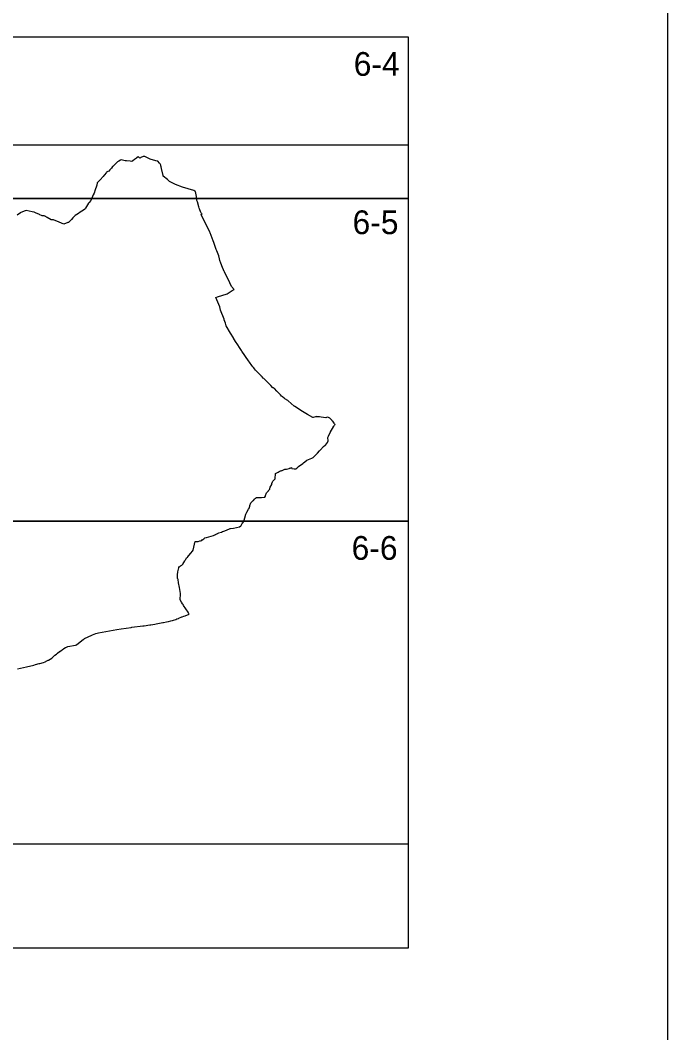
# Model space of a CAD drawing. Extents: x -447352 to -425530, y -1135906 to -1125104.
# Drawn here: x -441555.1 to -441304.5, y -1126663.9 to -1126271.9 of the extents above; entities that cross this region are included whole.
import ezdxf

# ---------------------------------------------------------------- set-up
doc = ezdxf.new("R2010")
doc.units = 0
for name, color, linetype in [('Vrstva 1', 7, 'Continuous'), ('Vrstva 10', 7, 'Continuous'), ('Vrstva 4', 7, 'Continuous')]:
    doc.layers.add(name, color=color, linetype=linetype)

msp = doc.modelspace()

# ---------------------------------------------------------------- linework, layer by layer
at = {"layer": 'Vrstva 1'}
msp.add_lwpolyline([(-442789.49, -1126016.81), (-442789.49, -1127066.81), (-441304.49, -1127066.81), (-441304.49, -1126016.81)], close=True, dxfattribs=at)
msp.add_lwpolyline([(-441556.2, -1126523.09), (-441552.66, -1126522.22), (-441549.89, -1126521.55), (-441549.22, -1126521.34), (-441547.73, -1126520.98), (-441547.52, -1126520.92), (-441546.09, -1126520.53), (-441545.49, -1126520.27), (-441545.27, -1126520.17), (-441545.11, -1126520.11), (-441544.29, -1126519.66), (-441544.23, -1126519.62), (-441542.92, -1126518.84), (-441541.77, -1126517.79), (-441541.12, -1126517.29), (-441540.99, -1126517.18), (-441540.97, -1126517.17), (-441540.81, -1126517.04), (-441540.66, -1126516.94), (-441539.86, -1126516.38), (-441539.8, -1126516.34), (-441539.73, -1126516.29), (-441539.22, -1126515.94), (-441538.85, -1126515.68), (-441538.19, -1126515.22), (-441537.6, -1126514.81), (-441537.44, -1126514.84), (-441537.43, -1126514.84), (-441537.41, -1126514.82), (-441536.68, -1126514.43), (-441533.72, -1126513.85), (-441533.3, -1126513.7), (-441531.27, -1126512.07), (-441530.8, -1126511.73), (-441530.77, -1126511.71), (-441530.41, -1126511.45), (-441530.23, -1126511.33), (-441528.84, -1126510.63), (-441527.43, -1126509.99), (-441527.13, -1126509.84), (-441525.87, -1126509.38), (-441524.87, -1126509.13), (-441519.16, -1126508.07), (-441517.74, -1126507.81), (-441516.03, -1126507.56), (-441512.16, -1126506.99), (-441511.92, -1126506.96), (-441507.62, -1126506.44), (-441507.09, -1126506.38), (-441504.94, -1126506.02), (-441504.62, -1126505.97), (-441502.96, -1126505.7), (-441502.56, -1126505.63), (-441501.15, -1126505.34), (-441499.86, -1126505.07), (-441499.65, -1126505.03), (-441498.48, -1126504.8), (-441497.81, -1126504.67), (-441497.79, -1126504.67), (-441496.88, -1126504.46), (-441496.81, -1126504.44), (-441496.16, -1126504.28), (-441495.81, -1126504.17), (-441494.92, -1126503.88), (-441494.48, -1126503.73), (-441493.83, -1126503.49), (-441493.71, -1126503.45), (-441492.62, -1126502.96), (-441492.62, -1126502.96), (-441492.5, -1126502.92), (-441491.85, -1126502.69), (-441491.76, -1126502.66), (-441491.33, -1126502.5), (-441489.67, -1126501.92), (-441489.69, -1126501.87), (-441489.8, -1126501.7), (-441489.96, -1126501.47), (-441490.18, -1126501.15), (-441491.88, -1126498.51), (-441492.09, -1126498.16), (-441492.26, -1126497.89), (-441492.7, -1126497.18), (-441493.23, -1126496.33), (-441493.07, -1126493.97), (-441493.06, -1126493.88), (-441493.45, -1126491.58), (-441493.45, -1126491.56), (-441493.46, -1126491.54), (-441493.46, -1126491.54), (-441493.46, -1126491.51), (-441493.87, -1126489.68), (-441493.88, -1126489.49), (-441493.94, -1126488.69), (-441494.04, -1126488.41), (-441494.05, -1126488.39), (-441494.16, -1126488.17), (-441494.2, -1126488.09), (-441494.21, -1126487.71), (-441494.24, -1126487.01), (-441494.19, -1126486.52), (-441494.19, -1126486.5), (-441494.1, -1126485.64), (-441494.08, -1126485.53), (-441493.79, -1126483.89), (-441493.71, -1126483.81), (-441493.41, -1126483.47), (-441493.35, -1126483.4), (-441493.09, -1126483.28), (-441493.03, -1126483.22), (-441492.77, -1126483.02), (-441492.54, -1126482.84), (-441492.33, -1126482.68), (-441492.27, -1126482.64), (-441492.19, -1126482.51), (-441492.11, -1126482.39), (-441492, -1126482.22), (-441491.78, -1126481.89), (-441491.36, -1126481.24), (-441491.23, -1126480.99), (-441491.22, -1126480.98), (-441491.08, -1126480.69), (-441491.03, -1126480.6), (-441490.85, -1126480.27), (-441490.71, -1126480.12), (-441490.41, -1126479.81), (-441490.24, -1126479.63), (-441489.96, -1126479.28), (-441489.83, -1126479.11), (-441489.14, -1126478.26), (-441488.48, -1126477.45), (-441488.19, -1126477.09), (-441487.95, -1126475.92), (-441487.89, -1126475.69), (-441487.82, -1126475.41), (-441487.5, -1126474.1), (-441487.42, -1126473.82), (-441487.42, -1126473.79), (-441487.4, -1126473.74), (-441487.24, -1126473.73), (-441487.22, -1126473.73), (-441486.98, -1126473.73), (-441486.29, -1126473.71), (-441486.28, -1126473.71), (-441486.25, -1126473.71), (-441485.57, -1126473.53), (-441485.37, -1126473.47), (-441484.95, -1126473.36), (-441484.93, -1126473.35), (-441484.87, -1126473.29), (-441484.57, -1126473.01), (-441484.45, -1126472.93), (-441484.11, -1126472.67), (-441483.69, -1126472.35), (-441483.62, -1126472.33), (-441483.06, -1126472.17), (-441480.36, -1126471.41), (-441479.77, -1126471.14), (-441479.44, -1126470.98), (-441479.39, -1126470.96), (-441479.29, -1126470.91), (-441478.93, -1126470.73), (-441478.88, -1126470.71), (-441478.85, -1126470.69), (-441478.84, -1126470.69), (-441478.81, -1126470.67), (-441478.5, -1126470.52), (-441478.44, -1126470.48), (-441478.33, -1126470.43), (-441477.25, -1126470.1), (-441476.82, -1126469.92), (-441476.3, -1126469.7), (-441475.29, -1126469.29), (-441473.87, -1126468.66), (-441473.73, -1126468.65), (-441472.6, -1126468.6), (-441470.2, -1126468.04), (-441469.67, -1126467.64), (-441469.6, -1126467.52), (-441469.51, -1126467.34), (-441469.25, -1126466.83), (-441468.9, -1126466.4), (-441468.88, -1126466.37), (-441468.67, -1126466.08), (-441468.56, -1126465.92), (-441468.55, -1126465.91), (-441468.01, -1126464.13), (-441468, -1126464.1), (-441467.8, -1126463.15), (-441467.54, -1126462.69), (-441467.35, -1126462.36), (-441466.8, -1126461.24), (-441466.42, -1126460.73), (-441466.39, -1126460.6), (-441466.32, -1126460.3), (-441466.29, -1126460.16), (-441466.23, -1126459.91), (-441466.21, -1126459.81), (-441465.89, -1126458.8), (-441465.88, -1126458.79), (-441465.59, -1126458.51), (-441464.93, -1126457.88), (-441464.88, -1126457.83), (-441464.41, -1126457.35), (-441464.15, -1126457.09), (-441464.05, -1126456.98), (-441463.68, -1126456.66), (-441463.64, -1126456.66), (-441463.63, -1126456.66), (-441463.22, -1126456.65), (-441463.05, -1126456.66), (-441462.42, -1126456.68), (-441461.71, -1126456.68), (-441460.74, -1126456.59), (-441460.71, -1126456.59), (-441460.46, -1126456.56), (-441460.24, -1126456.2), (-441460.19, -1126456.07), (-441460.17, -1126456.02), (-441460.15, -1126455.96), (-441459.79, -1126454.94), (-441459.65, -1126454.77), (-441459.55, -1126454.66), (-441459.51, -1126454.62), (-441459.45, -1126454.54), (-441459.33, -1126454.41), (-441459.06, -1126454.09), (-441458.97, -1126453.99), (-441458.87, -1126453.87), (-441458.53, -1126453.48), (-441458.46, -1126453.09), (-441458.4, -1126452.78), (-441458.33, -1126452.65), (-441457.78, -1126451.73), (-441457.67, -1126451.34), (-441457.48, -1126450.64), (-441457.36, -1126450.35), (-441457.07, -1126450.08), (-441456.52, -1126449.57), (-441456.45, -1126449.51), (-441456.35, -1126447.4), (-441455.33, -1126446.91), (-441454.93, -1126446.7), (-441454.68, -1126446.57), (-441454.39, -1126446.41), (-441454.17, -1126446.33), (-441453.83, -1126446.2), (-441453.78, -1126446.19), (-441452.69, -1126445.78), (-441452.68, -1126445.78), (-441452.19, -1126445.72), (-441452.11, -1126445.7), (-441451.08, -1126445.44), (-441450.93, -1126445.4), (-441450.84, -1126445.37), (-441450.67, -1126445.32), (-441450.14, -1126445.15), (-441450.14, -1126445.15), (-441450.13, -1126445.16), (-441450.13, -1126445.16), (-441450.1, -1126445.22), (-441449.97, -1126445.44), (-441449.09, -1126445.54), (-441448.89, -1126445.56), (-441448.53, -1126445.6), (-441448.44, -1126445.56), (-441448.01, -1126445.38), (-441447.36, -1126444.67), (-441445.72, -1126443.51), (-441445.63, -1126443.44), (-441445.46, -1126443.33), (-441444.95, -1126442.91), (-441444.2, -1126442.31), (-441442.93, -1126441.74), (-441442.31, -1126441.47), (-441441.77, -1126441.23), (-441441.71, -1126441.2), (-441440.06, -1126439.53), (-441439.22, -1126438.64), (-441438.86, -1126438.26), (-441437.67, -1126436.9), (-441437.07, -1126436.44), (-441437.02, -1126436.4), (-441436.18, -1126435.39), (-441435.98, -1126434.82), (-441436.07, -1126433.49), (-441435.85, -1126433), (-441435.21, -1126431.55), (-441433.75, -1126429.07), (-441433.72, -1126429.02), (-441433.72, -1126429.02), (-441433.7, -1126428.99), (-441433.67, -1126428.95), (-441433.52, -1126428.76), (-441433.26, -1126428.42), (-441433.52, -1126428.12), (-441433.66, -1126427.9), (-441434.13, -1126427.16), (-441434.33, -1126426.97), (-441434.48, -1126426.81), (-441434.67, -1126426.61), (-441435.25, -1126426.04), (-441436.1, -1126425.57), (-441436.55, -1126425.75), (-441436.88, -1126425.87), (-441438.63, -1126425.6), (-441439.24, -1126425.51), (-441439.38, -1126425.5), (-441439.97, -1126425.48), (-441440.35, -1126425.43), (-441440.51, -1126425.4), (-441440.55, -1126425.4), (-441440.58, -1126425.39), (-441440.58, -1126425.39), (-441440.61, -1126425.4), (-441440.71, -1126425.43), (-441440.84, -1126425.46), (-441441.74, -1126425.7), (-441441.81, -1126425.67), (-441443.88, -1126424.63), (-441445.9, -1126423.35), (-441448.81, -1126421.53), (-441448.97, -1126421.39), (-441449.01, -1126421.36), (-441449.1, -1126421.28), (-441450.24, -1126420.35), (-441451.39, -1126419.3), (-441451.5, -1126419.2), (-441452.71, -1126418.44), (-441452.99, -1126418.21), (-441453.62, -1126417.71), (-441453.93, -1126417.47), (-441454.43, -1126416.94), (-441455.15, -1126416.18), (-441455.3, -1126416.02), (-441455.76, -1126415.53), (-441456.73, -1126414.5), (-441456.93, -1126414.39), (-441456.93, -1126414.39), (-441457.11, -1126414.3), (-441457.31, -1126414.2), (-441458.14, -1126413.37), (-441458.77, -1126412.74), (-441459.95, -1126411.57), (-441460.88, -1126410.63), (-441461.04, -1126410.48), (-441461.48, -1126410.03), (-441461.72, -1126409.79), (-441461.81, -1126409.7), (-441461.85, -1126409.66), (-441462.37, -1126409.14), (-441463.01, -1126408.49), (-441463.09, -1126408.41), (-441463.11, -1126408.39), (-441463.26, -1126408.24), (-441464.09, -1126407.4), (-441464.47, -1126406.9), (-441464.75, -1126406.53), (-441465.07, -1126406.1), (-441465.43, -1126405.62), (-441466.38, -1126404.36), (-441466.75, -1126403.82), (-441469.29, -1126400.08), (-441469.46, -1126399.82), (-441470.23, -1126398.63), (-441470.9, -1126397.62), (-441471.74, -1126396.29), (-441472.54, -1126395.02), (-441472.62, -1126394.89), (-441473.71, -1126393.04), (-441475.39, -1126390.19), (-441475.39, -1126390.18), (-441475.39, -1126390.18), (-441475.4, -1126390.18), (-441475.73, -1126389.2), (-441476.18, -1126387.9), (-441476.24, -1126387.7), (-441477.62, -1126384.19), (-441477.91, -1126382.94), (-441479.39, -1126379.26), (-441478.76, -1126379.06), (-441475.04, -1126377.82), (-441473.07, -1126376.6), (-441472.89, -1126376.49), (-441472.83, -1126376.45), (-441472.63, -1126376.33), (-441472.36, -1126376.16), (-441473.28, -1126374.97), (-441474.69, -1126372.19), (-441475.44, -1126370.72), (-441475.97, -1126369.56), (-441475.99, -1126369.52), (-441476.05, -1126369.39), (-441476.06, -1126369.36), (-441476.08, -1126369.33), (-441476.12, -1126369.24), (-441476.45, -1126368.51), (-441476.77, -1126367.72), (-441477.48, -1126365.95), (-441477.89, -1126364.91), (-441478.04, -1126364.28), (-441478.3, -1126363.15), (-441479.04, -1126361.26), (-441479.24, -1126360.66), (-441480.18, -1126358.03), (-441480.45, -1126357.31), (-441481.64, -1126354.22), (-441481.71, -1126354.04), (-441481.74, -1126353.96), (-441485.09, -1126347.15), (-441484.78, -1126347.01), (-441484.76, -1126347), (-441484.86, -1126346.83), (-441484.94, -1126346.73), (-441485.11, -1126346.5), (-441485.17, -1126346.42), (-441485.78, -1126344.94), (-441485.83, -1126344.65), (-441485.93, -1126344.19), (-441485.94, -1126344.13), (-441486.45, -1126342.29), (-441486.75, -1126341.66), (-441486.76, -1126341.58), (-441486.8, -1126341.22), (-441486.94, -1126340.13), (-441487.22, -1126338.29), (-441487.28, -1126338.27), (-441487.58, -1126338.17), (-441487.96, -1126337.91), (-441487.97, -1126337.91), (-441492.27, -1126336.5), (-441495.06, -1126335.52), (-441496.37, -1126334.9), (-441497.34, -1126334.34), (-441498.06, -1126333.56), (-441499.74, -1126332.29), (-441499.8, -1126331.99), (-441500.38, -1126329.29), (-441500.53, -1126328.75), (-441500.71, -1126328.24), (-441500.76, -1126328.08), (-441501.01, -1126327.56), (-441501.26, -1126327.25), (-441501.84, -1126326.56), (-441502.59, -1126326.35), (-441504.77, -1126325.69), (-441506.86, -1126324.73), (-441507.48, -1126324.73), (-441508.43, -1126325.1), (-441508.56, -1126325.19), (-441508.63, -1126325.24), (-441508.77, -1126325.34), (-441508.81, -1126325.37), (-441508.83, -1126325.35), (-441509.04, -1126325.1), (-441509.29, -1126324.82), (-441509.37, -1126324.72), (-441509.46, -1126324.76), (-441509.97, -1126325.15), (-441510.16, -1126325.3), (-441510.83, -1126325.82), (-441511.58, -1126326.38), (-441511.92, -1126326.6), (-441512.51, -1126326.56), (-441513.99, -1126326.41), (-441514.45, -1126326.32), (-441516.04, -1126326), (-441516.34, -1126326.11), (-441516.9, -1126326.46), (-441517.45, -1126326.78), (-441517.94, -1126327.24), (-441518.47, -1126327.73), (-441518.87, -1126328.12), (-441518.88, -1126328.13), (-441519.21, -1126328.47), (-441519.34, -1126328.61), (-441519.85, -1126329.16), (-441520.3, -1126329.71), (-441520.46, -1126329.9), (-441520.82, -1126330.33), (-441521.56, -1126330.66), (-441521.58, -1126330.66), (-441521.78, -1126330.91), (-441522.64, -1126331.93), (-441523.02, -1126332.38), (-441524.15, -1126333.74), (-441524.16, -1126333.75), (-441525.4, -1126334.92), (-441525.52, -1126335.76), (-441525.57, -1126336.13), (-441525.61, -1126336.23), (-441526.09, -1126337.58), (-441526.53, -1126338.82), (-441526.56, -1126338.9), (-441526.86, -1126339.59), (-441527.79, -1126341.77), (-441527.81, -1126341.78), (-441528.38, -1126342.46), (-441528.68, -1126342.81), (-441528.68, -1126342.82), (-441529.02, -1126343.36), (-441529.89, -1126344.75), (-441529.98, -1126344.89), (-441530.15, -1126345.02), (-441530.68, -1126345.41), (-441531.29, -1126345.86), (-441531.29, -1126345.86), (-441532.26, -1126346.49), (-441532.39, -1126346.58), (-441532.57, -1126346.7), (-441533.87, -1126347.56), (-441533.88, -1126347.57), (-441534.14, -1126347.83), (-441534.26, -1126347.95), (-441534.48, -1126348.18), (-441534.76, -1126348.46), (-441535.33, -1126349.03), (-441536.49, -1126350.19), (-441536.69, -1126350.27), (-441538.19, -1126350.84), (-441541, -1126349.72), (-441541, -1126349.73), (-441541.01, -1126349.75), (-441541.92, -1126349.37), (-441542.23, -1126349.24), (-441542.25, -1126349.24), (-441542.64, -1126349.24), (-441543.12, -1126349.24), (-441544.68, -1126348.25), (-441544.94, -1126348.12), (-441545.23, -1126347.96), (-441545.29, -1126347.93), (-441545.33, -1126347.91), (-441545.87, -1126347.68), (-441545.92, -1126347.68), (-441545.93, -1126347.68), (-441546.08, -1126347.67), (-441546.2, -1126347.66), (-441546.51, -1126347.64), (-441546.53, -1126347.64), (-441546.53, -1126347.64), (-441546.64, -1126347.6), (-441546.88, -1126347.5), (-441547.48, -1126347.25), (-441547.64, -1126347.18), (-441549.16, -1126346.45), (-441549.78, -1126346.27), (-441550.45, -1126346.07), (-441552.77, -1126345.64), (-441552.78, -1126345.64), (-441553.18, -1126345.75), (-441554.92, -1126346.33), (-441555.05, -1126346.44), (-441556.26, -1126347.4)], dxfattribs=at)
at = {"layer": 'Vrstva 10'}
msp.add_lwpolyline([(-441404.9, -1126320.23), (-441404.9, -1126631.21), (-441737.77, -1126631.21), (-441737.77, -1126465.91), (-441717.4, -1126465.91), (-441717.4, -1126340.91), (-441717.4, -1126320.23), (-441404.9, -1126320.23)], dxfattribs=at)
at = {"layer": 'Vrstva 4'}
msp.add_line((-441717.4, -1126278.41), (-441404.9, -1126278.41), dxfattribs=at)
msp.add_lwpolyline([(-441404.9, -1126278.41), (-441404.9, -1126340.91), (-441561.15, -1126340.91), (-441561.15, -1126278.41)], dxfattribs=at)
for points in [[(-441404.9, -1126340.91), (-441404.9, -1126465.91), (-441561.15, -1126465.91), (-441561.15, -1126340.91)], [(-441404.9, -1126465.91), (-441404.9, -1126590.91), (-441561.15, -1126590.91), (-441561.15, -1126465.91)]]:
    msp.add_lwpolyline(points, close=True, dxfattribs=at)

# ---------------------------------------------------------------- texts
at = {"layer": 'Vrstva 1'}
for s, p in [('6-4', (-441426.03, -1126293.46)), ('6-5', (-441426.48, -1126354.75)), ('6-6', (-441426.85, -1126480.82))]:
    msp.add_text(s, height=9.2, dxfattribs=at).set_placement(p)

doc.saveas('drawing.dxf')
